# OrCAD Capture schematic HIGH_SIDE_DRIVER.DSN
size A
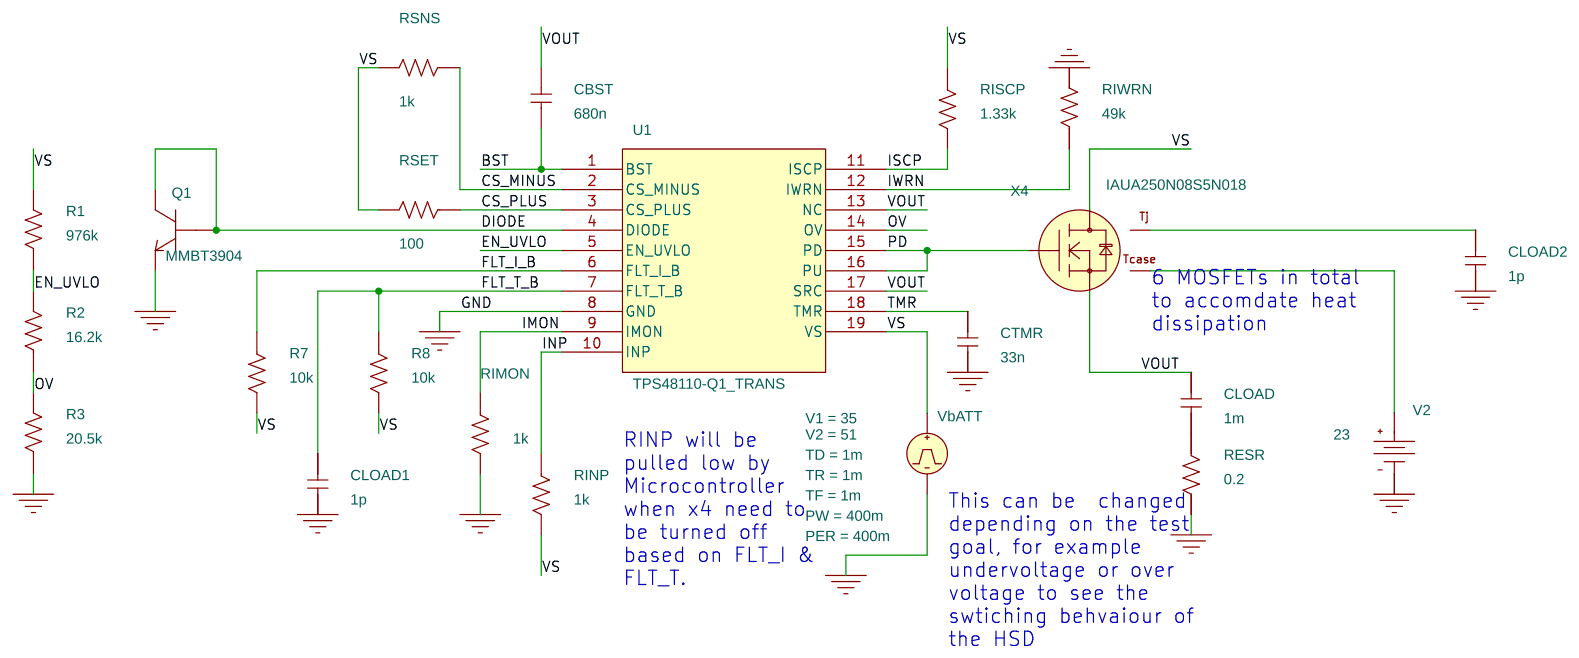
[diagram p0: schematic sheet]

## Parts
CBST  680n  [cap196]
CLOAD  1m  [cap196]
CLOAD1  1p  [cap196]
CLOAD2  1p  [cap196]
CTMR  33n  [cap196]
Q1  MMBT3904  [SOT23]
R1  976k  [AXRC05]
R2  16.2k  [AXRC05]
R3  20.5k  [AXRC05]
R7  10k  [AXRC05]
R8  10k  [AXRC05]
RESR  0.2  [AXRC05]
RIMON  1k  [AXRC05]
RINP  1k  [AXRC05]
RISCP  1.33k  [AXRC05]
RIWRN  49k  [AXRC05]
RSET  100  [AXRC05]
RSNS  1k  [AXRC05]
U1  TPS48110-Q1_TRANS
V2  VDC
VbATT  VPULSE
X4  IAUA250N08S5N018

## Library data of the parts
CBST = C: VOLTAGE: 50V
CLOAD CLOAD1 CLOAD2 CTMR = C
Q1 = MMBT3904
R1-R3 R7 R8 RESR RIMON RINP RISCP RIWRN RSET RSNS = R
U1 = TPS48110-Q1_TRANS
V2 = VDC: DC: 23
VbATT = VPULSE: PER: 400m; PW: 400m; TD: 1m; TF: 1m; TR: 1m; V1: 35; V2: 51
X4 = IAUA250N08S5N018

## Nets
0: CLOAD1.1 CLOAD2.1 CTMR.1 Q1.2(E) R3.1 RESR.2 RIMON.2 RIWRN.2 U1.8(GND) V2.1(-) VbATT.2(-)
BST: CBST.1 U1.1(BST)
CS_MINUS: RSNS.1 U1.2(CS_MINUS)
CS_PLUS: RSET.1 U1.3(CS_PLUS)
DIODE: Q1.1(B) Q1.3(C) U1.4(DIODE)
EN_UVLO: R1.1 R2.2 U1.5(EN_UVLO)
FLT_I_B: R7.1 U1.6(FLT_I_B)
FLT_T_B: CLOAD1.2 R8.1 U1.7(FLT_T_B)
IMON: RIMON.1 U1.9(IMON)
INP: RINP.1 U1.10(INP)
ISCP: RISCP.2 U1.11(ISCP)
IWRN: RIWRN.1 U1.12(IWRN)
OV: R2.1 R3.2 U1.14(OV)
PD: U1.15(PD) U1.16(PU) X4.2(gate)
TMR: CTMR.2 U1.18(TMR)
VOUT: CBST.2 CLOAD.2 U1.13(NC) U1.17(SRC) X4.3(source)
VS: R1.2 R7.2 R8.2 RINP.2 RISCP.1 RSET.2 RSNS.2 U1.19(VS) VbATT.1(+) X4.1(drain)
N03264: V2.0(+) X4.5(Tcase)
N06099: CLOAD.1 RESR.1
N07288: CLOAD2.2 X4.4(Tj)

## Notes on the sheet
- 6 MOSFETs in total
  to accomdate heat
  dissipation
- RINP will be
  pulled low by
  Microcontroller
  when x4 need to
  be turned off
  based on FLT_I &
  FLT_T.
- This can be  changed
  depending on the test
  goal, for example
  undervoltage or over
  voltage to see the
  swtiching behvaiour of
  the HSD
